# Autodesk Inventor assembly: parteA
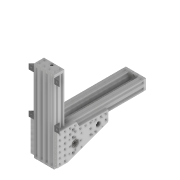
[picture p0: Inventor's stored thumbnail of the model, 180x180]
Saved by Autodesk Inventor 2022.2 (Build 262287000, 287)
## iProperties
Created: 2024-09
Part Number: parteA
Document SubType Name: Assembly
Designer: 18907419
Author: 18907419
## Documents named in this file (7)
- C:\Users\18907419\Desktop\trapano\parteA.iam
- C:\Users\18907419\Desktop\trapano\Z.ipt
- C:\Users\18907419\Desktop\trapano\Y.ipt
- C:\Users\18907419\Desktop\trapano\END4080T10 v29.ipt
- C:\Users\18907419\Desktop\trapano\connect120200T12 v47.ipt
- C:\Users\18907419\Desktop\trapano\Black Angle Corner Connector v3.ipt
- C:\Users\18907419\Documents\Inventor\Content Center Files\R2022\it-IT\BS 290 SKF(20)\BS 290 SKF - SKF 6001-2RZ.ipt
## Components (14 placed, 6 different names)
1. Z:1 — Coincidente:1, Allineato:1, Allineato:2, Coincidente:2, Allineato:3, Allineato:4, Coincidente:4, Allineato:7, Allineato:8, Coincidente:7, Allineato:14
2. Y:1 — Coincidente:1, Allineato:1, Allineato:2, Coincidente:3, Allineato:5, Allineato:6, Allineato:9, Allineato:10, Coincidente:5, Allineato:11, Coincidente:8, Allineato:15, Coincidente:9, Allineato:19, Coincidente:11, Coincidente:12
3. END4080T10 v29:1 — Coincidente:2, Allineato:3, Allineato:4
4. END4080T10 v29:2 — Coincidente:4, Allineato:7, Allineato:8, Coincidente:6
5. END4080T10 v29:3 — Coincidente:3, Allineato:5, Allineato:6, Allineato:16, Allineato:20
6. END4080T10 v29:4 — Allineato:9, Allineato:10, Coincidente:5
7. connect120200T12 v47:1 — Coincidente:7, Allineato:12, Allineato:13, Coincidente:10, Rotazionale:2
8. connect120200T12 v47:2 — Coincidente:6, Allineato:11, Allineato:12, Allineato:13, Allineato:14, Coincidente:13, Rotazionale:1
9. Black Angle Corner Connector v3:1 — Coincidente:8, Allineato:15, Allineato:16, Allineato:17
10. Black Angle Corner Connector v3:2 — Allineato:17, Coincidente:9, Coincidente:10
11. Black Angle Corner Connector v3:3 — Allineato:18, Coincidente:11, Allineato:20
12. Black Angle Corner Connector v3:4 — Allineato:18, Allineato:19, Coincidente:12, Coincidente:13
13. BS 290 SKF- con due guarnizioni a basso attrito SKF 6001-2RZ:1 — Rotazionale:1
14. BS 290 SKF- con due guarnizioni a basso attrito SKF 6001-2RZ:2 — Rotazionale:2
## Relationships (35: Flush 20, Mate 13, RevoluteJoint 2)
- Coincidente:1 [Mate]: Z:1 ↔ Y:1
- Allineato:1 [Flush]: Z:1 ↔ Y:1
- Allineato:2 [Flush]: Z:1 ↔ Y:1
- Coincidente:2 [Mate]: Z:1 ↔ END4080T10 v29:1
- Allineato:3 [Flush]: Z:1 ↔ END4080T10 v29:1
- Allineato:4 [Flush]: Z:1 ↔ END4080T10 v29:1
- Coincidente:3 [Mate]: Y:1 ↔ END4080T10 v29:3
- Allineato:5 [Flush]: Y:1 ↔ END4080T10 v29:3
- Allineato:6 [Flush]: Y:1 ↔ END4080T10 v29:3
- Coincidente:4 [Mate]: Z:1 ↔ END4080T10 v29:2
- Allineato:7 [Flush]: Z:1 ↔ END4080T10 v29:2
- Allineato:8 [Flush]: Z:1 ↔ END4080T10 v29:2
- Allineato:9 [Flush]: Y:1 ↔ END4080T10 v29:4
- Allineato:10 [Flush]: Y:1 ↔ END4080T10 v29:4
- Coincidente:5 [Mate]: Y:1 ↔ END4080T10 v29:4
- Coincidente:6 [Mate]: END4080T10 v29:2 ↔ connect120200T12 v47:2
- Allineato:11 [Flush]: Y:1 ↔ connect120200T12 v47:2
- Coincidente:7 [Mate]: Z:1 ↔ connect120200T12 v47:1
- Allineato:12 [Flush]: connect120200T12 v47:1 ↔ connect120200T12 v47:2
- Allineato:13 [Flush]: connect120200T12 v47:1 ↔ connect120200T12 v47:2
- Allineato:14 [Flush]: Z:1 ↔ connect120200T12 v47:2
- Coincidente:8 [Mate]: Y:1 ↔ Black Angle Corner Connector v3:1
- Allineato:15 [Flush]: Y:1 ↔ Black Angle Corner Connector v3:1
- Allineato:16 [Flush]: END4080T10 v29:3 ↔ Black Angle Corner Connector v3:1
- Allineato:17 [Flush]: Black Angle Corner Connector v3:1 ↔ Black Angle Corner Connector v3:2
- Coincidente:9 [Mate]: Y:1 ↔ Black Angle Corner Connector v3:2
- Coincidente:10 [Mate]: connect120200T12 v47:1 ↔ Black Angle Corner Connector v3:2
- Allineato:18 [Flush]: Black Angle Corner Connector v3:3 ↔ Black Angle Corner Connector v3:4
- Allineato:19 [Flush]: Y:1 ↔ Black Angle Corner Connector v3:4
- Coincidente:11 [Mate]: Y:1 ↔ Black Angle Corner Connector v3:3
- Allineato:20 [Flush]: END4080T10 v29:3 ↔ Black Angle Corner Connector v3:3
- Coincidente:12 [Mate]: Y:1 ↔ Black Angle Corner Connector v3:4
- Coincidente:13 [Mate]: connect120200T12 v47:2 ↔ Black Angle Corner Connector v3:4
- Rotazionale:1 [RevoluteJoint]: connect120200T12 v47:2 ↔ BS 290 SKF- con due guarnizioni a basso attrito SKF 6001-2RZ:1
- Rotazionale:2 [RevoluteJoint]: connect120200T12 v47:1 ↔ BS 290 SKF- con due guarnizioni a basso attrito SKF 6001-2RZ:2
